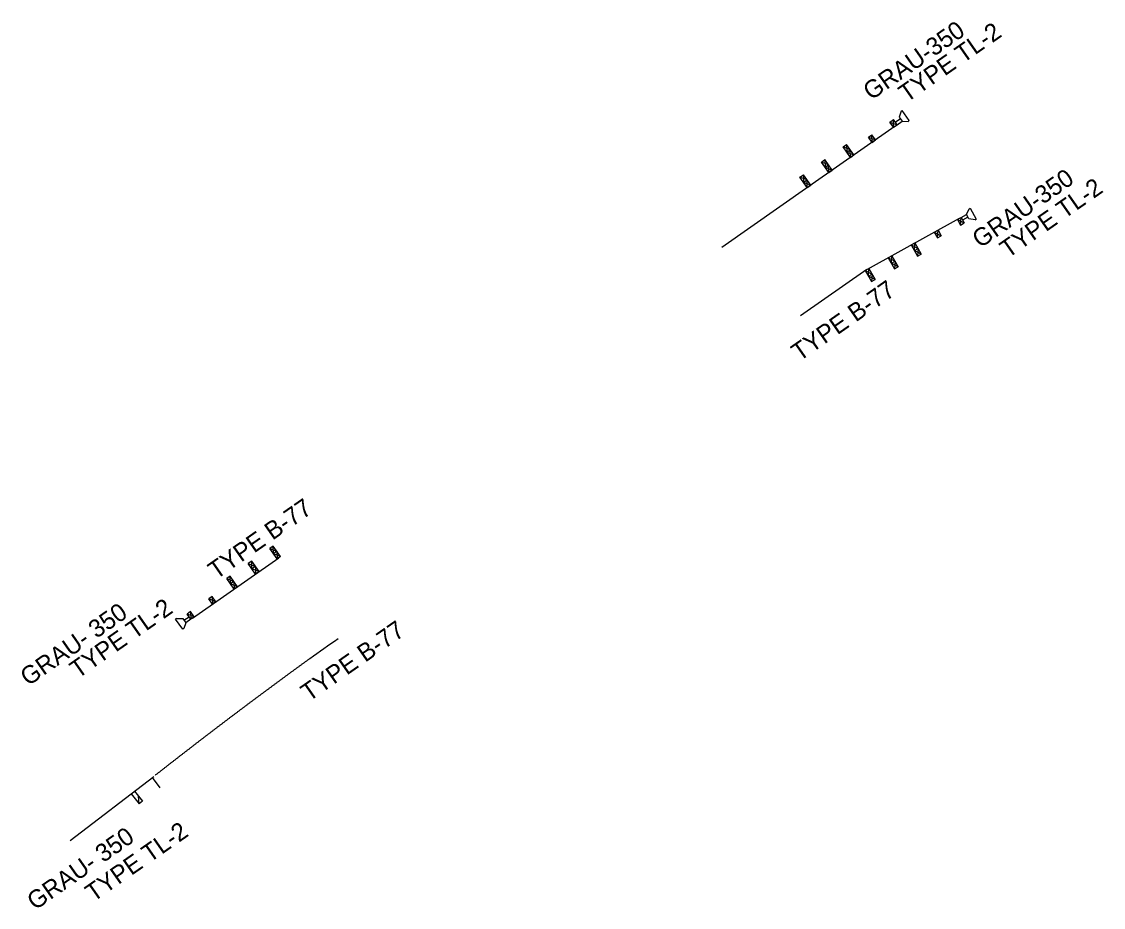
# Model space of a CAD drawing. Extents: x 1033697 to 1037131, y 657437 to 660507.
# Drawn here: x 1033790 to 1034303, y 657437 to 657858 of the extents above; entities that cross this region are included whole.
import ezdxf

# ---------------------------------------------------------------- set-up
doc = ezdxf.new("R2010")
doc.units = 0
doc.layers.add('Old_Level_63', color=7, linetype='Continuous')

msp = doc.modelspace()

# ---------------------------------------------------------------- linework, layer by layer
at = {"layer": 'Old_Level_63'}
for p, q in [((1034202.16, 657810.45), (1034203.8, 657811.6)), ((1034205.54, 657809.11), (1034203.8, 657811.6)), ((1034203.9, 657807.96), (1034203.81, 657811.6)), ((1034207.11, 657811.99), (1034204.71, 657810.3)), ((1034207.48, 657815.57), (1034206.54, 657812.82)), ((1034206.54, 657812.82), (1034207.94, 657810.81)), ((1034207.48, 657815.57), (1034207.98, 657815.92)), ((1034211.36, 657811.11), (1034207.98, 657815.92)), ((1034204.72, 657808.54), (1034163.74, 657779.89)), ((1034203.9, 657807.96), (1034202.16, 657810.45)), ((1034202.17, 657810.45), (1034205.54, 657809.11)), ((1034203.9, 657807.96), (1034205.54, 657809.11)), ((1034205.53, 657809.12), (1034207.94, 657810.81)), ((1034207.94, 657810.81), (1034210.85, 657810.76)), ((1034210.85, 657810.76), (1034211.36, 657811.11)), ((1034191.92, 657803.29), (1034193.56, 657804.44)), ((1034193.66, 657800.8), (1034191.92, 657803.29)), ((1034191.92, 657803.29), (1034195.3, 657801.95)), ((1034195.3, 657801.95), (1034193.56, 657804.44)), ((1034193.66, 657800.8), (1034193.56, 657804.44)), ((1034193.66, 657800.8), (1034195.3, 657801.95)), ((1034179.94, 657798.62), (1034181.57, 657799.76)), ((1034183.41, 657793.64), (1034179.94, 657798.62)), ((1034183.31, 657797.28), (1034179.94, 657798.62)), ((1034185.05, 657794.79), (1034181.57, 657799.76)), ((1034181.57, 657799.76), (1034181.67, 657796.13)), ((1034181.67, 657796.13), (1034183.31, 657797.28)), ((1034181.67, 657796.13), (1034185.05, 657794.79)), ((1034183.41, 657793.64), (1034183.31, 657797.28)), ((1034169.69, 657791.46), (1034171.33, 657792.6)), ((1034173.17, 657786.48), (1034169.69, 657791.46)), ((1034173.07, 657790.11), (1034169.69, 657791.46)), ((1034174.81, 657787.63), (1034171.33, 657792.6)), ((1034171.33, 657792.6), (1034171.43, 657788.97)), ((1034183.41, 657793.64), (1034185.05, 657794.79)), ((1034171.43, 657788.97), (1034173.07, 657790.11)), ((1034171.43, 657788.97), (1034174.81, 657787.63)), ((1034173.17, 657786.48), (1034173.07, 657790.11)), ((1034173.17, 657786.48), (1034174.81, 657787.63)), ((1034159.44, 657784.29), (1034161.08, 657785.44)), ((1034162.92, 657779.32), (1034159.44, 657784.29)), ((1034162.82, 657782.95), (1034159.44, 657784.29)), ((1034164.56, 657780.46), (1034161.08, 657785.44)), ((1034161.08, 657785.44), (1034161.18, 657781.81)), ((1034161.18, 657781.81), (1034162.82, 657782.95)), ((1034161.18, 657781.81), (1034164.56, 657780.46)), ((1034162.92, 657779.32), (1034162.82, 657782.95)), ((1034122.35, 657750.96), (1034163.72, 657779.91)), ((1034162.92, 657779.32), (1034164.56, 657780.46)), ((1034235.92, 657765.14), (1034238.49, 657766.56)), ((1034239.19, 657765.3), (1034236.62, 657763.88)), ((1034238.49, 657766.56), (1034239.72, 657769.21)), ((1034239.68, 657764.42), (1034238.49, 657766.56)), ((1034239.72, 657769.21), (1034240.26, 657769.51)), ((1034240.26, 657769.51), (1034243.1, 657764.36)), ((1034235.03, 657764.67), (1034191.31, 657740.42)), ((1034234.16, 657764.19), (1034235.91, 657765.16)), ((1034234.16, 657764.19), (1034235.63, 657761.53)), ((1034234.16, 657764.19), (1034237.38, 657762.5)), ((1034235.63, 657761.53), (1034235.91, 657765.16)), ((1034235.63, 657761.53), (1034237.38, 657762.5)), ((1034235.91, 657765.16), (1034237.38, 657762.5)), ((1034242.57, 657764.06), (1034239.68, 657764.42)), ((1034242.57, 657764.06), (1034243.1, 657764.36)), ((1034223.23, 657758.13), (1034224.98, 657759.1)), ((1034223.23, 657758.13), (1034224.7, 657755.47)), ((1034223.23, 657758.13), (1034226.45, 657756.44)), ((1034224.7, 657755.47), (1034224.98, 657759.1)), ((1034224.7, 657755.47), (1034226.45, 657756.44)), ((1034224.98, 657759.1), (1034226.45, 657756.44)), ((1034212.3, 657752.06), (1034214.05, 657753.03)), ((1034212.3, 657752.06), (1034215.24, 657746.75)), ((1034212.3, 657752.06), (1034215.52, 657750.38)), ((1034213.77, 657749.41), (1034214.05, 657753.03)), ((1034213.77, 657749.41), (1034215.52, 657750.38)), ((1034214.05, 657753.03), (1034216.99, 657747.72)), ((1034215.52, 657750.38), (1034215.24, 657746.75)), ((1034201.37, 657746), (1034203.12, 657746.97)), ((1034201.37, 657746), (1034204.31, 657740.69)), ((1034201.37, 657746), (1034204.59, 657744.32)), ((1034202.84, 657743.35), (1034203.12, 657746.97)), ((1034203.12, 657746.97), (1034206.06, 657741.66)), ((1034216.99, 657747.72), (1034213.77, 657749.41)), ((1034215.24, 657746.75), (1034216.99, 657747.72)), ((1034159.68, 657718.49), (1034191.25, 657740.52)), ((1034190.44, 657739.94), (1034192.18, 657740.91)), ((1034190.44, 657739.94), (1034193.38, 657734.63)), ((1034190.44, 657739.94), (1034193.66, 657738.25)), ((1034191.91, 657737.28), (1034192.18, 657740.91)), ((1034192.18, 657740.91), (1034195.13, 657735.6)), ((1034202.84, 657743.35), (1034204.59, 657744.32)), ((1034206.06, 657741.66), (1034202.84, 657743.35)), ((1034204.59, 657744.32), (1034204.31, 657740.69)), ((1034204.31, 657740.69), (1034206.06, 657741.66)), ((1034191.91, 657737.28), (1034193.66, 657738.25)), ((1034195.13, 657735.6), (1034191.91, 657737.28)), ((1034193.66, 657738.25), (1034193.38, 657734.63)), ((1034193.38, 657734.63), (1034195.13, 657735.6)), ((1033909.46, 657609.04), (1033907.82, 657607.9)), ((1033911.3, 657602.92), (1033907.82, 657607.9)), ((1033907.82, 657607.9), (1033911.2, 657606.56)), ((1033912.94, 657604.07), (1033909.46, 657609.04)), ((1033909.56, 657605.41), (1033909.46, 657609.04)), ((1033911.2, 657606.56), (1033909.56, 657605.41)), ((1033911.2, 657606.56), (1033911.3, 657602.92)), ((1033871.13, 657574.85), (1033912.12, 657603.49)), ((1033899.21, 657601.88), (1033897.57, 657600.74)), ((1033902.69, 657596.91), (1033899.21, 657601.88)), ((1033899.31, 657598.25), (1033899.21, 657601.88)), ((1033912.94, 657604.07), (1033909.56, 657605.41)), ((1033912.94, 657604.07), (1033911.3, 657602.92)), ((1033901.05, 657595.76), (1033897.57, 657600.74)), ((1033897.57, 657600.74), (1033900.95, 657599.39)), ((1033900.95, 657599.39), (1033899.31, 657598.25)), ((1033902.69, 657596.91), (1033899.31, 657598.25)), ((1033900.95, 657599.39), (1033901.05, 657595.76)), ((1033902.69, 657596.91), (1033901.05, 657595.76)), ((1033888.97, 657594.72), (1033887.33, 657593.58)), ((1033890.81, 657588.6), (1033887.33, 657593.58)), ((1033887.33, 657593.58), (1033890.71, 657592.23)), ((1033892.45, 657589.74), (1033888.97, 657594.72)), ((1033889.07, 657591.09), (1033888.97, 657594.72)), ((1033890.71, 657592.23), (1033889.07, 657591.09)), ((1033892.45, 657589.74), (1033889.07, 657591.09)), ((1033890.71, 657592.23), (1033890.81, 657588.6)), ((1033892.45, 657589.74), (1033890.81, 657588.6)), ((1033880.46, 657585.07), (1033878.82, 657583.93)), ((1033880.56, 657581.44), (1033878.82, 657583.93)), ((1033882.2, 657582.58), (1033878.82, 657583.93)), ((1033882.2, 657582.58), (1033880.46, 657585.07)), ((1033880.46, 657585.07), (1033880.56, 657581.44)), ((1033882.2, 657582.58), (1033880.56, 657581.44)), ((1033867.07, 657573.79), (1033869.48, 657575.47)), ((1033871.95, 657575.42), (1033868.57, 657576.77)), ((1033870.22, 657577.91), (1033868.58, 657576.77)), ((1033870.32, 657574.28), (1033868.58, 657576.77)), ((1033870.21, 657577.91), (1033870.32, 657574.28)), ((1033871.95, 657575.42), (1033870.22, 657577.91)), ((1033871.95, 657575.42), (1033870.32, 657574.28)), ((1033863.58, 657574.68), (1033863.08, 657574.33)), ((1033866.44, 657569.5), (1033863.08, 657574.33)), ((1033863.58, 657574.68), (1033866.49, 657574.62)), ((1033866.49, 657574.62), (1033867.89, 657572.61)), ((1033867.89, 657572.61), (1033866.94, 657569.86)), ((1033870.3, 657574.29), (1033867.89, 657572.61)), ((1033866.94, 657569.86), (1033866.44, 657569.5)), ((1033813.08, 657469.17), (1033852.71, 657499.66)), ((1033851.92, 657499.05), (1033855.62, 657494.23)), ((1033842.01, 657491.42), (1033845.72, 657486.61)), ((1033843.6, 657492.64), (1033847.3, 657487.83)), ((1033845.72, 657486.61), (1033845.45, 657490.24)), ((1033847.3, 657487.83), (1033845.72, 657486.61))]:
    msp.add_line(p, q, dxfattribs=at)
msp.add_spline([(1033853.51, 657500.27), (1033854.51, 657501.06), (1033855.52, 657501.84), (1033856.52, 657502.63), (1033857.52, 657503.42), (1033858.53, 657504.2), (1033859.53, 657504.99), (1033860.54, 657505.77), (1033861.55, 657506.56), (1033862.55, 657507.34), (1033863.56, 657508.13), (1033864.57, 657508.91), (1033865.57, 657509.69), (1033866.58, 657510.47), (1033867.59, 657511.25), (1033868.6, 657512.03), (1033869.61, 657512.81), (1033870.62, 657513.59), (1033871.63, 657514.37), (1033872.64, 657515.15), (1033873.65, 657515.93), (1033874.66, 657516.71), (1033875.67, 657517.48), (1033876.69, 657518.26), (1033877.7, 657519.04), (1033878.71, 657519.81), (1033879.73, 657520.59), (1033880.74, 657521.36), (1033881.75, 657522.13), (1033882.77, 657522.91), (1033883.78, 657523.68), (1033884.8, 657524.45), (1033885.82, 657525.22), (1033886.83, 657526), (1033887.85, 657526.77), (1033888.87, 657527.54), (1033889.89, 657528.31), (1033890.9, 657529.07), (1033891.92, 657529.84), (1033892.94, 657530.61), (1033893.96, 657531.38), (1033894.98, 657532.14), (1033896, 657532.91), (1033897.02, 657533.68), (1033898.04, 657534.44), (1033899.07, 657535.21), (1033900.09, 657535.97), (1033901.11, 657536.73), (1033902.13, 657537.5), (1033903.16, 657538.26), (1033904.18, 657539.02), (1033905.21, 657539.78), (1033906.23, 657540.54), (1033907.26, 657541.3), (1033908.28, 657542.06), (1033909.31, 657542.82), (1033910.33, 657543.58), (1033911.36, 657544.34), (1033912.39, 657545.1), (1033913.41, 657545.85), (1033914.44, 657546.61), (1033915.47, 657547.37), (1033916.5, 657548.12), (1033917.53, 657548.88), (1033918.56, 657549.63), (1033919.59, 657550.38), (1033920.63, 657551.14), (1033921.67, 657551.9), (1033922.71, 657552.66), (1033923.75, 657553.42), (1033924.79, 657554.19), (1033925.83, 657554.95), (1033926.87, 657555.71), (1033940.2, 657565.06)], degree=3, dxfattribs=at)

# ---------------------------------------------------------------- texts
for s, p in [('GRAU-350', (1034193.24, 657820.51)), ('TYPE TL-2', (1034210.13, 657819.47)), ('GRAU-350', (1034245.01, 657750.28)), ('TYPE TL-2', (1034258.2, 657745.51)), ('TYPE B-77', (1034159.22, 657696.53)), ('TYPE B-77', (1033882.36, 657592.89)), ('GRAU- 350', (1033793.15, 657542.3)), ('TYPE TL-2', (1033816.69, 657545.83)), ('TYPE B-77', (1033926.35, 657534.89)), ('GRAU- 350', (1033796.37, 657435.8)), ('TYPE TL-2', (1033824.06, 657439.74))]:
    msp.add_text(s, height=8.438, rotation=34.9512, dxfattribs=at).set_placement(p)

doc.saveas('drawing.dxf')
